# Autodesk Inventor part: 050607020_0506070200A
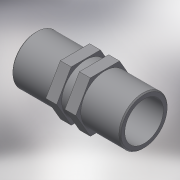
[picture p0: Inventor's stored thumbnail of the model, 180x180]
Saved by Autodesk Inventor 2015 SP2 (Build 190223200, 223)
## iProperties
Created: 2017-05
Part Number: 050607020_0506070200A
Material: Generic
Description: PLASSON NIPPLE 2"-2"
Document SubType Name: Modeling
Designer: KIM
Density: 1 g/cm^3
Appearance: Default
Author: KIM
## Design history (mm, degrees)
derived "050607.ipt"
feature "Solid1::050607.ipt"
tag "TaggingFeature1"
body "Solid1"
other parameters: "d0" = 71, "d1" = 59.614, "d2" = 65, "d3" = 47.6912, "d4" = 26, "d5" = 26, "d6" = 7.1, "d8" = 0.71, "d12" = 0, "H_" = 71, "R_" = 59.614, "E_" = 65, "l_2" = 26
